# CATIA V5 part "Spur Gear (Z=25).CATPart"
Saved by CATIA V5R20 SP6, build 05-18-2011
Part number: Spur Gear (Z=25)
Bounding box of the stored display mesh (mm): x 0 to 11, y -26.983 to 26.983, z -26.869 to 26.99
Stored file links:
  E:\#01 CATIA Lecture Materials\#06 DMU\#10 Kinematics Joints\#002 Gear Joint(Spur Gear)\Spur Gear (Z=25).CATPart
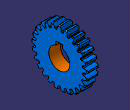
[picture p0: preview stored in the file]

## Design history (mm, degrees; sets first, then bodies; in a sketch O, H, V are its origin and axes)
Parameters
  a = 20 deg
  m = 2 mm
  Z = 25
  rp = 25 mm {= m * Z / 2}
  ra = 27 mm {= rp + m}
  rb = 23.4923 mm {= rp * cos( a  )}
  rf = 22.5 mm {= rp -1.25 * m}
  rc = 0.76 mm {= m * 0.38}
  c = 0.115855 {= sqrt( 1 / ( cos( a ) * cos( a ) ) - 1 ) / PI}
  phi = 4.454 deg
Set1 "Reference Data"
  Point1 "Center Point": (0, 0, 0)
  Line1 "Axis (X Direction)": type PtDir, RefPoint Point1, Direction yz-plane, Start 0, End 20
  Point2 "Involute Curve Point_01": (0, 0, 23.4923)
  Point3 "Involute Curve Point_02": (0, 0.2404, 24.6232)
  Point4 "Involute Curve Point_03": (0, 1.8668, 27.6818)
  Point5 "Involute Curve Point_04": (0, 5.9915, 31.7209)
  Point6 "Involute Curve Point_05": (0, 13.2199, 35.336)
  Curve1 "Involute Curve": Elements (Point2; Point3; Point4; Point5; Point6)
  Extrapol1: ToExtrapol Point2, Support Curve1, Length 4 {= m * 2}
  Rotate1: ToTransfor Extrapol1, Axis Line1, Angle 4.454 {= phi}
  Circle1: type CtrRad, Start 0, End 180, Center Point1, Support yz-plane, Radius 27 {= ra}, FirstDirection (0, 1, 0)
  Circle2: type CtrRad, Start 0, End 180, Center Point1, Support yz-plane, Radius 22.5 {= rf}, FirstDirection (0, 1, 0)
  Corner1: Element1 Rotate1, Element2 Circle2, Radius 0.76 {= rc}
  Set2 "Corner Operation Body"
    Sketch1 on yz-plane, origin (0, 0, 0), H (0, 1, 0), V (0, 0, 1)
      projected curve E1 from edge of Rotate1
      projected curve E2 from edge of Rotate1
      projected curve E3 from edge of Rotate1
      point P1 (-1.9655, 19.4232)
      projected arc E4 centre (0, 0) radius 22.5 from (22.5, 0) to (-22.5, 0) ccw from Circle2
      projected arc E5 centre (0, 0) radius 22.5 from (-1.8613, 22.4229) to (-2.5128, 22.3592) ccw from Circle2
      projected arc E6 centre (0, 0) radius 22.5 from (-2.5128, 22.3592) to (-22.5, 0) ccw from Circle2
      point P3 (22.5, 0)
      arc A1 centre (-2.5977, 23.1145) radius 0.76 from (-1.8382, 23.0876) to (-2.5128, 22.3592) cw
      radius A1 = 0.76 {= rc}
      coincidence: E1 P1, E4 P3
      tangency: A1 E1, A1 E4
    Extrude1: Element1 Rotate1, Lim1 5, Lim2 5, Direction yz-plane
    Extrude2: Element1 Circle2, Lim1 5, Lim2 5, Direction yz-plane
    Intersect1: ToIntersect1 Extrude1, ToIntersect2 yz-plane
    Intersect2: ToIntersect1 Extrude2, ToIntersect2 yz-plane
    Corner2: Element1 Intersect1, Element2 Intersect2, Radius 0.76 {= rc}
  Plane1 "Plane.1(ZX Plane Rotate=9deg)": type Angle, RefPlane zx-plane, Direction Line1, Angle 7.2 {= 180deg / Z}
  Symmetry1: ToTransfor Corner1, Reference Plane1
  Split1: ToCut Rotate1, Cutting (Circle1; Corner1)
  Symmetry2: ToTransfor Split1, Reference zx-plane
  Point7: type OnCurve, Support Symmetry2, Ratio 1
  Point8: type OnCurve, Support Split1, Ratio 1
  Point9: type OnCurve, Support Corner1, Ratio 1
  Point10: type OnCurve, Support Symmetry1, Ratio 1
  Circle3: type 2PointsRad, Start 0, End 180, FirstPoint Point8, SecondPoint Point7, Support yz-plane, Radius 27 {= ra}
  Circle4: type 2PointsRad, Start 0, End 180, FirstPoint Point9, SecondPoint Point10, Support yz-plane, Radius 22.5 {= rf}
  Join1: Elements (Symmetry2; Circle3; Split1; Corner1; Circle4; Symmetry1)
  CircPattern1: of Join1, instances 25 {= Z}, angular step 14.4 {= 360.0*1 deg/CircPattern1.AngularNumber}, axis from Line1
  Join2: Elements (Join1; CircPattern1)
Body1 (main body)
  Body2 "Spur Gear Body"
    Pad1: profile Join2, length 11
    Sketch2 on zx-plane, origin (0, 0, 0), H (-1, 0, 0), V (0, 0, 1)
      axis line L1 (0, 0) -> (6.502, 0)
      line L2 (0, 0) -> (0, 26)
      line L3 (-1, 27) -> (-10, 27)
      line L4 (-11, 26) -> (-11, 0)
      point P2 (-11, 0)
      line L5 (-11, 0) -> (0, 0)
      line L6 (-10, 27) -> (-11, 26)
      point P3 (-11, 26)
      line L7 (-1, 27) -> (0, 26)
      point P4 (0, 26)
      construction line L8 (-11, 26) -> (0, 26)
      distance H L3 = 27 {= ra}
      distance L2 L4 = 11 {= Pad1.FirstLimit.Length}
      angle L2 L7 = 45 {= Sketch2.angle(L6 L4)}
      angle L6 L4 = 45
      distance L3 L8 = 1
      horizontal: L1 H, L3 H, L5 H, L8 H
      vertical: L2 V, L4 V
      coincidence: P2 H, P3 L4, P4 L2, P3 L6, P4 L7
    Groove1: profile Sketch2, axis Sketch2.L1, angle 360
  Assemble1: tool Body2
  Body3 "Key Hole Body"
    Sketch3 on yz-plane, origin (0, 0, 0), H (0, 1, 0), V (0, 0, 1)
      arc A1 centre (0, 0) radius 10 from (-3, 9.5394) to (3, 9.5394) ccw
      line L1 (-3, 12.8) -> (3, 12.8)
      line L2 (3, 12.8) -> (3, 9.5394)
      line L3 (-3, 9.5394) -> (-3, 12.8)
      radius A1 = 10
      distance L3 L2 = 6
      distance L1 A1 = 22.8
      horizontal: L1 H
      vertical: L2 V, L3 V
      symmetry: L3 L2 V
    Pad2: profile Sketch3, direction (1, 0, 0), length 11 {= Pad1.FirstLimit.Length}
  Remove1: tool Body3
